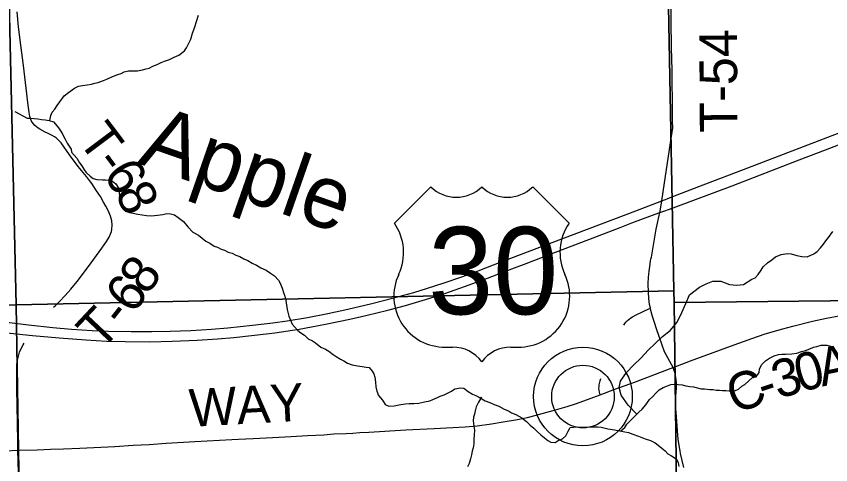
# Model space of a CAD drawing. Extents: x 0 to 34, y 0 to 22.
# Drawn here: x 22.282 to 23.511, y 13.381 to 14.057 of the extents above; entities that cross this region are included whole.
import ezdxf

# ---------------------------------------------------------------- set-up
doc = ezdxf.new("R2010")
doc.units = 0
for name, color, linetype in [('GM_X_County_Road', 7, 'Continuous'), ('GM_X_County_Road_Text', 7, 'Continuous'), ('GM_X_Minor_River', 7, 'Continuous'), ('GM_X_Minor_River_Text', 7, 'Continuous'), ('GM_X_Section', 7, 'Continuous'), ('GM_X_Township_Road', 7, 'Continuous'), ('GM_X_Township_Road_Text', 7, 'Continuous'), ('GM_X_Unincorporated', 7, 'Continuous'), ('GM_X_Unincorporated_Location', 7, 'Continuous'), ('GM_X_US_Route', 7, 'Continuous'), ('GM_X_US_Shield', 7, 'Continuous')]:
    doc.layers.add(name, color=color, linetype=linetype)

msp = doc.modelspace()

# ---------------------------------------------------------------- linework, layer by layer
at = {"layer": 'GM_X_County_Road'}
for points in [[(23.2734, 13.5275), (23.2992, 13.5374), (23.3597, 13.5596), (23.3917, 13.5712), (23.4121, 13.578), (23.4387, 13.586), (23.4536, 13.59), (23.4835, 13.5972), (23.5047, 13.6018), (23.5261, 13.6057)], [(23.1632, 13.4863), (23.1853, 13.4946), (23.2162, 13.5059), (23.2704, 13.5263), (23.2734, 13.5275)], [(23.2892, 13.3766), (23.2844, 13.3978), (23.2835, 13.402), (23.2825, 13.4071), (23.2808, 13.4194), (23.2796, 13.4318), (23.278, 13.4535), (23.2774, 13.4658), (23.2771, 13.4752), (23.2774, 13.4845), (23.2782, 13.4969), (23.2782, 13.504), (23.2778, 13.5092), (23.2762, 13.5182), (23.2747, 13.5231), (23.2734, 13.5275)], [(22.2847, 13.4027), (22.3136, 13.4035), (22.3339, 13.4043), (22.3534, 13.4048), (22.378, 13.4061), (22.4308, 13.4085), (22.4586, 13.4102), (22.4828, 13.4116), (22.5081, 13.4133), (22.5514, 13.4159), (22.6072, 13.4189), (22.6172, 13.4194), (22.6284, 13.42), (22.6397, 13.4206), (22.6689, 13.4221), (22.6967, 13.4235), (22.7213, 13.425), (22.7459, 13.4262), (22.7613, 13.4273), (22.7799, 13.4281), (22.7901, 13.4287), (22.8006, 13.4294), (22.8139, 13.4302), (22.8697, 13.4334), (22.9124, 13.4353), (22.941, 13.437), (22.9592, 13.4379), (22.9775, 13.4397), (22.999, 13.4425), (23.0167, 13.4454), (23.0383, 13.4491), (23.0477, 13.451), (23.0534, 13.4521), (23.0589, 13.4534), (23.092, 13.4626), (23.1131, 13.4685), (23.1275, 13.4733), (23.1537, 13.4826), (23.1632, 13.4863)], [(22.1189, 13.3969), (22.1478, 13.3979), (22.2038, 13.3999), (22.266, 13.402), (22.2847, 13.4027)]]:
    msp.add_lwpolyline(points, dxfattribs=at)
at = {"layer": 'GM_X_Minor_River'}
for points in [[(22.3328, 13.8998), (22.3341, 13.9077), (22.3364, 13.9123), (22.3401, 13.9169), (22.3438, 13.9223), (22.3479, 13.9281), (22.3543, 13.9373), (22.3607, 13.9423), (22.3701, 13.9485), (22.3758, 13.9516), (22.3822, 13.9525), (22.3891, 13.9537), (22.3955, 13.9549), (22.4005, 13.9561), (22.4058, 13.9573), (22.4137, 13.9601), (22.4186, 13.9624), (22.4262, 13.9656), (22.4353, 13.9691), (22.4402, 13.9707), (22.4451, 13.9734), (22.4516, 13.9746), (22.4652, 13.9748), (22.4728, 13.9761), (22.4781, 13.9777), (22.4827, 13.9789), (22.488, 13.9816), (22.4948, 13.9843), (22.5005, 13.9875), (22.5058, 13.9894), (22.5133, 13.9918), (22.5205, 13.9953), (22.5273, 13.9984), (22.536, 14.005), (22.539, 14.0096), (22.5419, 14.0154), (22.5456, 14.0226), (22.5482, 14.0318), (22.5504, 14.0379), (22.5518, 14.0425), (22.5533, 14.0478), (22.5573, 14.0585)], [(22.28, 13.9137), (22.2984, 13.9035), (22.3034, 13.9032), (22.3148, 13.9026), (22.3202, 13.9015), (22.3255, 13.9008), (22.332, 13.9001), (22.3381, 13.8979), (22.3439, 13.8915), (22.3473, 13.887), (22.3512, 13.8802), (22.3559, 13.872), (22.359, 13.8659), (22.3648, 13.8569), (22.3657, 13.852), (22.3734, 13.8429), (22.3777, 13.8362), (22.3808, 13.8316), (22.3843, 13.8267), (22.3877, 13.8215), (22.3935, 13.8159), (22.3981, 13.8125), (22.4039, 13.8111), (22.4122, 13.8104), (22.4168, 13.8105), (22.4221, 13.8102), (22.4271, 13.8083), (22.4325, 13.8042), (22.436, 13.7989), (22.4372, 13.7925), (22.4377, 13.7849), (22.4381, 13.7804), (22.4389, 13.7743), (22.4417, 13.7683), (22.4467, 13.7634), (22.4528, 13.7612), (22.4585, 13.7601), (22.4654, 13.7587), (22.4719, 13.7576), (22.4787, 13.7566), (22.4863, 13.7563), (22.4951, 13.7572), (22.503, 13.7584), (22.5091, 13.7597), (22.5148, 13.759), (22.5209, 13.7575), (22.5263, 13.7538), (22.5344, 13.7475), (22.5409, 13.7396), (22.5483, 13.7317), (22.5571, 13.7269), (22.5628, 13.7224), (22.5682, 13.7179), (22.574, 13.7149), (22.5805, 13.7105), (22.5858, 13.709), (22.5912, 13.7061), (22.5965, 13.7046), (22.6019, 13.7016), (22.6076, 13.6998), (22.6134, 13.6969), (22.6195, 13.6947), (22.6252, 13.6913), (22.6317, 13.6887), (22.6379, 13.685), (22.6448, 13.6817), (22.6509, 13.678), (22.6593, 13.6743), (22.6658, 13.6698), (22.6716, 13.6657), (22.6778, 13.6593), (22.6801, 13.6544), (22.6832, 13.6473), (22.686, 13.6393), (22.6872, 13.6348), (22.6888, 13.6287), (22.69, 13.6215), (22.6909, 13.6151), (22.6933, 13.6049), (22.6957, 13.5988), (22.6984, 13.5928), (22.7026, 13.5883), (22.7069, 13.5834), (22.7115, 13.58), (22.7169, 13.5763), (22.7226, 13.5707), (22.7288, 13.5677), (22.7337, 13.5647), (22.7418, 13.558), (22.7487, 13.5551), (22.7537, 13.5521), (22.7602, 13.5469), (22.7648, 13.5439), (22.7713, 13.5398), (22.7763, 13.5376), (22.7817, 13.5342), (22.7889, 13.5313), (22.797, 13.5299), (22.8042, 13.5288), (22.8099, 13.5282), (22.8145, 13.5275)], [(23.3794, 13.6527), (23.3918, 13.6607), (23.3967, 13.6627), (23.4016, 13.6676), (23.4057, 13.6741), (23.4091, 13.6795), (23.4155, 13.6852), (23.422, 13.6899), (23.4276, 13.6941), (23.436, 13.698), (23.4458, 13.6992), (23.4512, 13.6988), (23.4599, 13.6963), (23.4675, 13.6948), (23.4755, 13.6945), (23.4854, 13.6987), (23.4903, 13.7026), (23.4956, 13.708), (23.5001, 13.7133), (23.5035, 13.7183), (23.5076, 13.7233), (23.514, 13.7328)], [(23.2183, 13.4572), (23.2053, 13.4709), (23.1949, 13.4859), (23.1918, 13.4973), (23.1937, 13.5068), (23.203, 13.5201), (23.2132, 13.5308), (23.2248, 13.5423), (23.2354, 13.5538), (23.2459, 13.5637), (23.2572, 13.574), (23.2685, 13.5832), (23.2794, 13.5958), (23.2865, 13.6103), (23.2921, 13.624), (23.2977, 13.6373), (23.3127, 13.6484), (23.3229, 13.6534), (23.3328, 13.6576), (23.3452, 13.6577), (23.3582, 13.6525), (23.3692, 13.6515), (23.3794, 13.6527)], [(23.3811, 13.5016), (23.3934, 13.5128), (23.3984, 13.5136), (23.4029, 13.5201), (23.4032, 13.5251), (23.4066, 13.5316), (23.4126, 13.5377), (23.4183, 13.5415), (23.4255, 13.545), (23.4323, 13.547), (23.4376, 13.5474), (23.4429, 13.5474), (23.4521, 13.5479), (23.4597, 13.5491), (23.4669, 13.5518), (23.4729, 13.553), (23.4794, 13.5557), (23.4847, 13.558), (23.49, 13.5592), (23.4964, 13.5612), (23.5052, 13.5613), (23.5128, 13.559)], [(22.8145, 13.5275), (22.8191, 13.5222), (22.8218, 13.5177), (22.823, 13.5128), (22.8239, 13.5052), (22.8247, 13.4983), (22.826, 13.4919), (22.8287, 13.4855), (22.8345, 13.478), (22.8388, 13.4716), (22.8441, 13.469), (22.8525, 13.4698), (22.8624, 13.4719), (22.8696, 13.4727), (22.8749, 13.4732), (22.8821, 13.4733), (22.8897, 13.4738), (22.8981, 13.4758), (22.906, 13.4774), (22.9106, 13.479), (22.9174, 13.4821), (22.9219, 13.4841), (22.9276, 13.4864), (22.9325, 13.4888), (22.9385, 13.4919), (22.9438, 13.4954), (22.9522, 13.4966), (22.9575, 13.4963), (22.964, 13.4915), (22.9706, 13.4874), (22.9755, 13.4855), (22.982, 13.4818), (22.9893, 13.4774), (22.9966, 13.4748), (23.0031, 13.4715), (23.0103, 13.4693), (23.0184, 13.4645), (23.0245, 13.4619), (23.0295, 13.4593), (23.036, 13.4567), (23.0448, 13.4515), (23.0517, 13.4459), (23.0575, 13.4407), (23.0629, 13.4362), (23.0683, 13.4306), (23.0733, 13.4261), (23.079, 13.4212), (23.084, 13.4175), (23.0886, 13.4149), (23.0951, 13.4146), (23.0996, 13.4173), (23.1064, 13.4197), (23.1113, 13.4247), (23.115, 13.4316), (23.1176, 13.4369), (23.1229, 13.4377), (23.1503, 13.4381), (23.1595, 13.4379), (23.1648, 13.4375), (23.1747, 13.435), (23.1846, 13.4336), (23.1926, 13.4322), (23.2002, 13.4304), (23.2056, 13.4293), (23.2121, 13.4272), (23.2209, 13.4239), (23.2308, 13.4198), (23.2388, 13.4173), (23.2461, 13.4139), (23.2507, 13.4102), (23.2561, 13.4057), (23.2611, 13.402), (23.2653, 13.3975), (23.2707, 13.3945), (23.2776, 13.39), (23.2807, 13.3844), (23.2819, 13.3783)], [(23.1942, 13.4318), (23.2002, 13.4369), (23.2031, 13.4419), (23.2095, 13.448), (23.2148, 13.4538), (23.2215, 13.4603), (23.2264, 13.4646), (23.232, 13.4711), (23.2373, 13.4792), (23.2425, 13.4838), (23.247, 13.4888), (23.2523, 13.4938), (23.2583, 13.4973), (23.2644, 13.5), (23.2697, 13.5016), (23.2746, 13.5024), (23.2868, 13.5011), (23.2921, 13.5), (23.2982, 13.499), (23.304, 13.4983), (23.3154, 13.4954), (23.3207, 13.4951), (23.3283, 13.4944), (23.3333, 13.4941), (23.3382, 13.4934), (23.3432, 13.4931), (23.3478, 13.4928), (23.3527, 13.4928), (23.3577, 13.4921), (23.3626, 13.4922), (23.3672, 13.493), (23.3717, 13.495), (23.3766, 13.4992), (23.3811, 13.5016)], [(22.9829, 13.4813), (22.9839, 13.483), (22.9795, 13.475), (22.9761, 13.4681), (22.9747, 13.462), (22.9732, 13.457), (22.9721, 13.4525), (22.9715, 13.4471), (22.9723, 13.4392), (22.9732, 13.4331), (22.9729, 13.4262), (22.9726, 13.4186), (22.9723, 13.4122), (22.9716, 13.4065), (22.9701, 13.4011), (22.9691, 13.3958), (22.9676, 13.3897), (22.9654, 13.3828), (22.9628, 13.3779)]]:
    msp.add_lwpolyline(points, dxfattribs=at)
at = {"layer": 'GM_X_Section'}
for points in [[(23.2551, 14.663), (23.9946, 14.6733), (23.9771, 14.1383), (23.9802, 13.6328), (23.2745, 13.6253), (23.274, 13.6432)], [(22.2584, 14.6473), (23.2551, 14.663), (23.274, 13.6432), (22.2822, 13.6222)], [(21.2696, 14.6358), (22.2584, 14.6473), (22.2822, 13.6222), (21.2938, 13.6104)], [(23.274, 13.6432), (23.2745, 13.6253), (23.2871, 12.632), (22.2979, 12.6206), (22.2822, 13.6222)], [(23.2745, 13.6253), (23.9802, 13.6328), (23.9982, 12.6247), (23.2872, 12.6207), (23.2871, 12.632)], [(22.2822, 13.6222), (22.2979, 12.6206), (21.3125, 12.6129), (21.2938, 13.6104)]]:
    msp.add_lwpolyline(points, close=True, dxfattribs=at)
at = {"layer": 'GM_X_Township_Road'}
for p, q in [((23.2691, 13.8663), (23.2725, 13.8889)), ((23.2579, 13.7926), (23.2691, 13.8663)), ((22.2867, 13.3325), (22.2847, 13.4027))]:
    msp.add_line(p, q, dxfattribs=at)
for points in [[(23.2725, 13.8889), (23.2724, 13.8982), (23.2722, 13.9185), (23.272, 13.9337), (23.2718, 13.9537), (23.2715, 13.9756), (23.2708, 14.0096), (23.2702, 14.05), (23.2704, 14.0561), (23.2702, 14.0686), (23.2702, 14.0779), (23.2701, 14.0965), (23.2701, 14.1429), (23.2694, 14.174), (23.2686, 14.2143), (23.2679, 14.2546), (23.2672, 14.2855), (23.2668, 14.309), (23.2665, 14.3321), (23.2662, 14.3569), (23.2664, 14.3656)], [(22.3385, 13.6186), (22.3408, 13.6206), (22.3475, 13.6271), (22.3561, 13.6361), (22.3646, 13.6454), (22.3742, 13.6574), (22.391, 13.6796), (22.4112, 13.7072), (22.4183, 13.7175), (22.4223, 13.7242), (22.425, 13.7299), (22.4259, 13.7328), (22.4265, 13.7361), (22.4267, 13.7422), (22.4263, 13.7484), (22.4244, 13.7559), (22.4214, 13.763), (22.4171, 13.7706), (22.4136, 13.777), (22.4091, 13.7852), (22.4031, 13.7941), (22.3995, 13.7995), (22.396, 13.8048), (22.3925, 13.8094), (22.3879, 13.8156), (22.3756, 13.8305), (22.3623, 13.8484), (22.3498, 13.8662), (22.347, 13.8694), (22.343, 13.8732), (22.3397, 13.8754), (22.3363, 13.8774), (22.3293, 13.8807), (22.3258, 13.8824), (22.3176, 13.8868), (22.315, 13.8885), (22.3125, 13.8904), (22.3102, 13.8924), (22.3081, 13.8947), (22.3063, 13.8972), (22.3048, 13.8999), (22.3036, 13.9028), (22.3027, 13.9057), (22.302, 13.9088), (22.3016, 13.9119), (22.2998, 13.9273), (22.2971, 13.9489), (22.293, 13.9828), (22.2892, 14.0136), (22.2857, 14.0414), (22.2833, 14.064)], [(23.2406, 13.694), (23.2476, 13.7359), (23.253, 13.7611), (23.2535, 13.7632), (23.2559, 13.7789), (23.2579, 13.7926)], [(23.2388, 13.617), (23.2377, 13.6224), (23.2365, 13.6317), (23.2358, 13.641), (23.2356, 13.6535), (23.2361, 13.6637), (23.2363, 13.6676), (23.2369, 13.6728), (23.2383, 13.6832), (23.2392, 13.6888), (23.2396, 13.691), (23.2398, 13.6924), (23.2406, 13.694)], [(23.1987, 13.5911), (23.2004, 13.5937), (23.2023, 13.5962), (23.2044, 13.5985), (23.2068, 13.6005), (23.2092, 13.6024), (23.2118, 13.6041), (23.2173, 13.607), (23.2257, 13.6107), (23.2311, 13.6133), (23.2388, 13.617)], [(23.2734, 13.5275), (23.2601, 13.551), (23.2565, 13.5614), (23.2479, 13.5857), (23.2448, 13.5952), (23.242, 13.6042), (23.2395, 13.6132), (23.2388, 13.617)], [(22.2847, 13.4027), (22.2846, 13.4157), (22.2836, 13.47), (22.2832, 13.495), (22.2828, 13.5107), (22.2828, 13.5263), (22.2831, 13.5325), (22.2839, 13.5386), (22.2853, 13.5446), (22.2871, 13.5505), (22.2895, 13.5562), (22.2923, 13.5617), (22.294, 13.5643)], [(23.1632, 13.4863), (23.1618, 13.4905), (23.1614, 13.4932), (23.1612, 13.4963), (23.1614, 13.4981), (23.1617, 13.5011), (23.1629, 13.5072), (23.164, 13.5108)]]:
    msp.add_lwpolyline(points, dxfattribs=at)
at = {"layer": 'GM_X_Unincorporated'}
for radius in [0.0744, 0.0472]:
    msp.add_circle((23.1371, 13.4837), radius, dxfattribs=at)
at = {"layer": 'GM_X_Unincorporated_Location'}
msp.add_line((23.1371, 13.4837), (23.1371, 13.4837), dxfattribs=at)
at = {"layer": 'GM_X_US_Route'}
for p, q in [((23.2559, 13.7789), (23.2641, 13.782)), ((23.253, 13.7611), (23.2606, 13.7637))]:
    msp.add_line(p, q, dxfattribs=at)
for points in [[(23.2729, 13.7854), (23.3185, 13.803), (23.3795, 13.8262), (23.5303, 13.884), (23.629, 13.9216), (23.7101, 13.9528), (23.7827, 13.9805), (23.8437, 14.0037), (23.9306, 14.0371), (23.9888, 14.0589), (24.0613, 14.0867), (24.1252, 14.1111), (24.1861, 14.1345), (24.2529, 14.1599), (24.3573, 14.1999), (24.4211, 14.2246), (24.4936, 14.2524), (24.5219, 14.2631), (24.5779, 14.2842), (24.6331, 14.3051), (24.6579, 14.3141)], [(23.2606, 13.7637), (23.2662, 13.7657), (23.273, 13.7682), (23.307, 13.7806), (23.3622, 13.8016), (23.4635, 13.8408), (23.4926, 13.8519), (23.6144, 13.8985)], [(22.2141, 13.6022), (22.3005, 13.592), (22.3375, 13.588), (22.3654, 13.5855), (22.3964, 13.5834), (22.4213, 13.5824), (22.4554, 13.5819), (22.4865, 13.5817), (22.5145, 13.5821), (22.5456, 13.5833), (22.5766, 13.5853), (22.6014, 13.5874), (22.6385, 13.5911), (22.6693, 13.5949), (22.6909, 13.598), (22.7216, 13.6031), (22.7521, 13.6088), (22.7825, 13.6153), (22.8188, 13.6239), (22.8519, 13.6324), (22.8818, 13.6408), (22.9027, 13.6471), (22.9263, 13.6548), (22.9557, 13.6649), (22.979, 13.6734), (23.0139, 13.6867), (23.0719, 13.7088), (23.2171, 13.7639), (23.2559, 13.7789)], [(23.2641, 13.782), (23.2714, 13.7849), (23.2729, 13.7854)], [(22.2636, 13.5804), (22.3068, 13.5758), (22.347, 13.572), (22.3872, 13.569), (22.4182, 13.5673), (22.4462, 13.5665), (22.4834, 13.5662), (22.5175, 13.567), (22.5548, 13.5685), (22.5857, 13.5706), (22.6105, 13.5729), (22.6414, 13.5761), (22.6722, 13.5799), (22.709, 13.5855), (22.7274, 13.5887), (22.7487, 13.5927), (22.7852, 13.6004), (22.8094, 13.6057), (22.8426, 13.6139), (22.8696, 13.6211), (22.8993, 13.63), (22.9289, 13.6393), (22.9582, 13.6495), (22.9932, 13.6623), (23.0194, 13.6721), (23.0338, 13.6778), (23.0512, 13.6844), (23.0629, 13.6888), (23.0774, 13.6943), (23.089, 13.6987), (23.1064, 13.7052), (23.1209, 13.7108), (23.1354, 13.7163), (23.176, 13.732), (23.1934, 13.7386), (23.2108, 13.7454), (23.2282, 13.752), (23.2515, 13.7606), (23.253, 13.7611)]]:
    msp.add_lwpolyline(points, dxfattribs=at)
at = {"layer": 'GM_X_US_Shield'}
for p, q in [((22.9076, 13.7999), (22.8526, 13.745)), ((23.1163, 13.745), (23.0614, 13.7999)), ((22.9295, 13.5582), (22.9405, 13.5582)), ((23.0284, 13.5582), (23.0394, 13.5582))]:
    msp.add_line(p, q, dxfattribs=at)
for centre, radius, start, end in [((22.946, 13.8391), 0.0549, 225.573, 314.427), ((23.0229, 13.8391), 0.0549, 225.573, 314.427), ((22.7896, 13.7009), 0.0769, 334.5471, 35.0009), ((23.1793, 13.7009), 0.0769, 144.9991, 205.4529), ((22.9287, 13.6351), 0.0769, 154.8319, 270.6383), ((23.0402, 13.6351), 0.0769, 269.3617, 25.1681), ((22.9405, 13.5033), 0.0549, 36.8699, 90), ((23.0284, 13.5033), 0.0549, 90, 143.1301)]:
    msp.add_arc(centre, radius, start, end, dxfattribs=at)

# ---------------------------------------------------------------- texts
at = {"layer": 'GM_X_County_Road_Text'}
for s, height, rotation, p in [('0', 0.0568, 15.1533, (23.4648, 13.4896)), ('A', 0.0568, 11.9065, (23.4978, 13.4986)), ('3', 0.0568, 16.2317, (23.4315, 13.4799)), ('C', 0.0568, 19.8384, (23.3663, 13.4571)), ('WAY', 0.05682, 3.164, (22.5445, 13.4379)), ('-', 0.0568, 18.2696, (23.4099, 13.4728))]:
    msp.add_text(s, height=height, rotation=rotation, dxfattribs=at).set_placement(p)
at = {"layer": 'GM_X_Minor_River_Text'}
msp.add_text('Apple', height=0.09472, rotation=340.7629, dxfattribs=at).set_placement((22.4636, 13.8358))
at = {"layer": 'GM_X_Township_Road_Text'}
for s, height, rotation, p in [('T-54', 0.05682, 90.3605, (23.3703, 13.8815)), ('T', 0.0568, 306.9266, (22.3737, 13.87)), ('-', 0.0568, 306.6022, (22.3991, 13.8362)), ('6', 0.0568, 303.0427, (22.4123, 13.8184)), ('8', 0.0568, 295.6495, (22.4303, 13.791)), ('8', 0.0568, 54.16, (22.4794, 13.6349)), ('6', 0.0568, 53.6451, (22.4583, 13.6062)), ('T', 0.0568, 46.723, (22.41, 13.5512)), ('-', 0.0568, 51.8658, (22.4428, 13.5864))]:
    msp.add_text(s, height=height, rotation=rotation, dxfattribs=at).set_placement(p)
at = {"layer": 'GM_X_US_Shield'}
msp.add_text('30', height=0.13184, dxfattribs=at).set_placement((22.9036, 13.6077))

doc.saveas('drawing.dxf')
